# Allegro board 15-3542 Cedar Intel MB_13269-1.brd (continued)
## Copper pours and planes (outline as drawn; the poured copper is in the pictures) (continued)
RTC_AUX_S5 on TOP: 120.05,54.21 117.96,56.3 117.96,59.73 117.6,60.08 117.6,61.14 114.82,63.93 114.82,67.06 114.12,67.76 114.12,68.9 113.1,69.92 113.1,72.01 113.23,72.14 113.87,72.14 113.99,72.01 113.99,70.62 114.75,69.86 114.75,69.41 115.01,69.16 115.01,67.98 115.94,67.05 115.94,63.92 117.12,62.74 117.12,62.5 117.37,62.25 117.96,62.25 118.36,62.65 119.54,62.65 119.64,62.55 119.64,61.47 119.64,61.47 119.64,60.26 120.34,59.55 121.54,59.55 123.27,61.29 124.01,61.29 124.15,61.14 124.15,60.49 122.71,59.05 119.48,59.05 119.3,58.87 119.3,57.42 121.05,55.67 122.07,55.67 122.15,55.59 122.15,54.52 121.83,54.21 ; 5 cut-outs
SLEEVE on BOTTOM: 32.87,14.82 31.46,16.24 31.46,17.01 31.48,17.03 34.24,17.03 35.67,15.61 35.67,15.04 35.46,14.82
SLEEVE_R on TOP: 22.49,4.77 22.35,4.91 22.35,5.74 22.15,5.95 20.91,5.95 20.7,6.16 20.7,6.97 20.88,7.16 23.53,7.16 23.69,6.99 23.69,4.86 23.61,4.77
SP_PLLVDD on TOP: 169.77,101.21 169.67,101.31 169.67,101.89 169.44,102.12 168.42,102.12 168.31,102.23 168.31,107.85 168.09,108.07 168.09,110.36 168.22,110.48 169.49,110.48 169.74,110.23 169.74,103.12 170.51,102.35 170.51,101.31 170.41,101.21 ; 4 cut-outs
TP_VDD on TOP: 134.14,73.8 134.14,73.14 134.16,73.12 134.39,73.12 134.41,73.14 134.41,73.8 134.8,73.8 134.82,73.78 134.82,72.57 134.75,72.49 133.97,72.49 133.42,73.04 132.72,73.04 132.37,73.39 132.37,74.5 132.46,74.59 133.19,74.59 133.27,74.51 133.27,74.02 133.49,73.8
TPAN_VDD_F on TOP: 31.87,70.89 31.75,71.01 31.75,75.41 30.61,76.55 30.61,77.58 30.77,77.74 31.11,77.74 31.67,77.18 33.02,77.18 34.19,76.01 34.19,71.09 33.98,70.89 ; 2 cut-outs
TPS51216_PHS_SET on BOTTOM: 93.83,16.5 93.72,16.6 93.72,18.46 93.75,18.49 94.36,18.49 94.41,18.45 94.41,17.59 94.54,17.47 95.17,17.47 95.27,17.37 95.27,16.58 95.2,16.5
USB20_VCCA on TOP: 39.52,32.3 39.39,32.43 39.39,34.83 39.59,35.02 41.42,35.02 41.56,34.89 41.56,32.51 41.35,32.3
USB20_VCCA on TOP: 23.62,30.88 23.43,31.07 23.43,33.45 23.4,33.48 23.4,36.57 21.28,38.69 16.6,38.69 16.22,39.07 16.22,42.8 14.37,44.65 11.73,44.65 11.47,44.91 11.47,46.85 11.64,47.02 16.24,47.02 20.27,42.99 24.31,42.99 24.5,42.8 24.5,40.59 25.53,39.56 25.53,31.85 25.69,31.69 27.36,31.69 27.41,31.64 27.41,30.93 27.36,30.88 ; 5 cut-outs
USB20_VCCA on BOTTOM: 24.01,30.95 23.86,31.11 23.86,36.09 29.18,41.41 35.56,41.41 37.36,39.61 37.36,37.22 40.85,33.74 40.85,32.55 40.5,32.2 35.78,32.2 34.18,33.8 34.18,36.8 34.67,37.29 34.67,38.2 33.94,38.93 30.21,38.93 26.84,35.55 26.84,31.11 26.68,30.95
USB20_VCCA on BOTTOM: 12.09,44.7 11.66,45.13 11.66,46.93 11.76,47.03 15.03,47.03 15.52,46.55 15.52,44.95 15.26,44.7
USB20_VCCB on TOP: 181.61,4.17 181.31,4.47 181.31,5.45 182.88,5.45 182.88,5.85 182.58,5.85 182.58,5.85 181.31,5.85 181.31,6.46 182.9,6.46 182.9,6.85 181.31,6.85 181.31,7.45 182.91,7.45 182.91,7.85 182.5,7.85 182.5,7.85 181.31,7.85 181.31,8.33 181.46,8.48 186.16,8.48 186.96,7.68 186.96,4.51 186.62,4.17
USB20_VCCB on BOTTOM: 150.08,1.99 149.82,2.25 149.82,4.38 149.95,4.52 154.88,4.52 156.77,6.41 156.77,7.65 156.84,7.71 159.68,7.71 160.77,8.8 163.93,8.8 165.02,7.71 166.59,7.71 168.47,9.58 169.51,9.58 172.36,12.44 181.65,12.44 186.95,7.13 186.95,5.56 186.91,5.52 181.34,5.52 181.13,5.73 181.13,8.78 180.17,9.74 173.5,9.74 168.89,5.12 159.14,5.12 156,1.99 ; 5 cut-outs
USB30_VCCC on TOP: 35.29,34.11 35.17,34.24 35.17,35.98 35.3,36.12 36.76,36.12 36.9,35.98 36.9,34.44 36.57,34.11
USB30_VCCC on TOP: 14.87,27.42 14.57,27.72 14.57,28.26 14.47,28.37 14.47,30.29 14.86,30.68 19.2,30.68 19.2,30.68 23.43,30.68 23.44,30.68 27.28,30.68 27.37,30.59 27.37,29.33 27.22,29.19 25.47,29.19 25.34,29.07 25.34,27.56 25.2,27.42 ; 6 cut-outs
USB30_VCCC on L3: 27.27,30.76 24.32,30.76 24.01,30.45 24.01,28.65 24.17,28.49 28.71,28.49 33.04,32.82 36.52,32.82 36.74,33.05 36.74,35.38 36.42,35.71 35.68,35.71 35.26,35.29 31.79,35.29
VGA_CORE on TOP: 164.23,110.74 164.16,110.8 164.16,111.76 163.65,112.27 163.65,113.91 164.03,114.29 164.54,114.29 164.92,113.91 165.93,113.91 166.19,114.17 166.57,114.17 166.82,113.91 167.84,113.91 168.09,114.17 168.6,114.17 168.86,113.91 169.85,113.91 170.1,114.17 170.57,114.17 170.64,114.1 170.64,113.55 170.4,113.31 170.22,113.31 170.07,113.15 170,113.15 169.74,112.9 168.86,112.9 168.6,113.15 168.09,113.15 167.97,113.02 166.82,113.02 166.7,113.15 164.28,113.15 164.03,112.9 164.03,112.64 164.54,112.13 166.44,112.13 166.57,112.01 166.57,111.5 166.44,111.37 165.17,111.37 164.92,111.12 164.92,110.86 164.79,110.74
VGA_CORE on TOP: 164.28,117.6 164.16,117.72 164.16,118.36 164.41,118.61 168.47,118.61 169.11,119.25 169.49,119.25 170.38,118.36 171.4,118.36 171.52,118.23 171.52,117.72 171.4,117.6 ; 5 cut-outs
VGA_CORE on TOP: 164.28,115.44 164.16,115.56 164.16,116.2 164.41,116.45 171.4,116.45 171.65,116.2 171.65,115.56 171.52,115.44 ; 1 cut-out
VGA_CORE on TOP: 174.19,69.66 173.68,70.17 173.68,91.86 170.35,95.19 160.98,95.19 160.72,95.46 160.72,99.32 160.73,99.33 160.73,104.51 160.98,104.76 160.98,104.79 162.38,104.79 163.09,104.08 165.78,104.08 166.08,103.78 166.08,102.62 165.82,102.35 164.3,102.35 164.08,102.13 164.08,101.21 164.43,100.86 166.82,100.86 167.33,100.35 172.72,100.35 173.2,99.86 173.2,99.1 173.59,98.71 176.15,98.71 176.16,98.71 176.86,98.71 179.36,96.21 182.7,96.21 183.67,95.24 183.67,93.59 182.06,91.99 182.06,83.89 180.26,82.08 180.26,70.63 179.3,69.66 ; 11 cut-outs
VGA_CORE on BOTTOM: 163.65,110.1 163.01,110.74 163.01,119.12 164.16,120.26 164.54,120.26 164.79,120.01 164.79,119.88 163.39,118.48 163.39,118.36 163.78,117.98 164.03,117.98 165.93,119.88 166.32,119.88 166.44,119.75 166.44,119.5 163.39,116.45 163.39,116.2 163.65,115.94 164.03,115.94 167.84,119.75 168.22,119.75 168.35,119.63 168.35,119.37 163.52,114.55 163.52,114.17 163.65,114.04 164.03,114.04 169.74,119.75 170,119.75 170.25,119.5 170.25,119.37 163.52,112.64 163.52,112.13 163.65,112.01 164.03,112.01 171.78,119.75 172.03,119.75 172.28,119.5 172.28,119.37 164.41,111.5 164.41,111.25 164.66,110.99 164.92,110.99 171.78,117.85 172.16,117.85 172.28,117.72 172.28,117.34 166.32,111.37 166.19,111.37 165.93,111.12 165.93,110.86 166.19,110.61 166.57,110.61 171.9,115.94 172.16,115.94 172.41,115.69 172.41,115.56 168.09,111.25 168.09,110.86 168.22,110.74 168.73,110.74 171.9,113.91 172.03,113.91 172.28,113.66 172.28,113.4 170,111.12 170,110.74 170.13,110.61 170.63,110.61 171.78,111.75 172.03,111.75 172.28,111.5 172.28,111.25 171.14,110.1
VGA_CORE on BOTTOM: 174.32,68.78 173.68,69.41 173.68,91.81 173.63,91.81 170.36,95.09 164.51,95.09 164.41,95.19 164.41,95.7 164.67,95.95 173.05,95.95 173.07,95.98 173.84,95.22 174.06,95.22 174.29,94.99 183.18,94.99 183.61,94.56 183.61,69.02 183.36,68.78
VGA_CORE on L2VCC: 174.27,69.73 173.75,70.25 173.75,91.71 170.33,95.13 163.35,95.13 162.57,95.91 162.57,118.48 163.6,119.51 173.1,119.51 174,118.61 174,113.4 184.16,103.24 184.16,94.25 181.75,91.84 181.75,83.97 179.97,82.19 179.97,70.76 178.94,69.73
VGA_CORE on L3: 163.35,105.27 162.99,105.63 162.99,118.97 163.47,119.45 170.56,119.45 172.82,117.19 172.82,114.67 173.23,114.27 173.23,111.9 172.51,111.19 172.51,109.8 172.05,109.34 172.05,108.63 178.2,102.48 178.2,102.43 179.09,101.54 181.18,101.54 185.49,97.22 185.49,78.94 186.26,78.17 186.26,70.17 185.49,69.41 174.06,69.41 173.68,69.79 173.68,91.89 170.41,95.17 161.72,95.17 160.73,96.16 160.73,101.08 163.35,103.7
VGA_CORE on L4: 183.59,78.3 175.33,70.05 174.19,70.05 173.68,70.55 173.68,91.86 170.41,95.14 163.83,95.14 162.63,96.33 162.63,103.45 163.4,104.21 163.4,117.54 163.9,118.05 168.73,118.05 169.36,117.42 169.36,110.05 168.73,109.42 168.73,108.27 176.6,100.4 181.05,100.4 183.59,97.86
VRAM_PWR_PH on BOTTOM: 162.13,56.71 161.36,57.47 161.36,58.11 161.24,58.23 160.22,58.23 160.09,58.36 160.09,59.38 160.22,59.5 161.36,59.5 162.51,60.65 165.05,60.65 165.17,60.52 165.17,56.84 165.05,56.71

Small or netless copper shapes (teardrops, artwork), in the pictures only: 14 on TOP, 2 on BOTTOM

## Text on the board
Ref Des/Silkscreen Bottom: F5401:1.1A/6V | X1801:24MHZ | X3001:25MHZ | X1901:32.768KHZ | F6201:0.5A/6V | X7601:27MHZ | 13269-1 | MADE IN TAIWAN | Cedar_Intel-MB | PWB. FX3MC REV:A00
User.Comments: KING_1 | KING
Ref Des/Silkscreen Top: F5203:1.1A/24V | F5201:1.1A/24V
User.26: HEADER:EMN compare:1=show;2=show;3=show;4=show
User.33: ByImpedance:100.0@_REF_L1=("4.0/6.0(L1)" "5.0/11.0(L1)")|_REF_L6=("4.0/6.0(L6)" "5.0/11.0(L6)")|Type="DP"|_REF_L4=("4.0/9.0(L4)")|_REF_L3=("4.0/9.0(L3)")|imp="100.0" | ByImpedance:110.0@_REF_L1=("4.0/12.0(L1)")|_REF_L6=("4.0/12.0(L6)")|Type="DP"|_REF_L4=("3.5/13.0(L4)")|_REF_L3=("3.5/13.0(L3)")|imp="110.0" | ByImpedance:27.4@_REF_L1=("16.0(L1)")|_REF_L6=("16.0(L6)")|Type="SE"|_REF_L4=("16.0(L4)")|_REF_L3=("16.0(L3)")|imp="27.4" | ByImpedance:33.0@_REF_L1=("12.0(L1)")|_REF_L6=("12.0(L6)")|Type="SE"|_REF_L4=("12.0(L4)")|_REF_L3=("12.0(L3)")|imp="33.0" | ByImpedance:35.0@_REF_L1=("11.0(L1)")|_REF_L6=("11.0(L6)")|Type="SE"|_REF_L4=("10.5(L4)")|_REF_L3=("10.5(L3)")|imp="35.0" | ByImpedance:37.5@_REF_L1=("10.0(L1)")|_REF_L6=("10.0(L6)")|Type="SE"|_REF_L4=("9.5(L4)")|_REF_L3=("9.5(L3)")|imp="37.5" | ByImpedance:40.0@_REF_L1=("8.5(L1)")|_REF_L6=("8.5(L6)")|Type="SE"|_REF_L4=("8.5(L4)")|_REF_L3=("8.5(L3)")|imp="40.0" | ByImpedance:45.0@_REF_L1=("7.0(L1)")|_REF_L6=("7.0(L6)")|Type="SE"|_REF_L4=("6.5(L4)")|_REF_L3=("6.5(L3)")|imp="45.0" | ByImpedance:48.0@_REF_L1=("6.0(L1)")|_REF_L6=("6.0(L6)")|Type="SE"|_REF_L4=("5.5(L4)")|_REF_L3=("5.5(L3)")|imp="48.0" | ByImpedance:50.0@_REF_L1=("5.5(L1)")|_REF_L6=("5.5(L6)")|Type="SE"|_REF_L4=("5.0(L4)")|_REF_L3=("5.0(L3)")|imp="50.0" | ByImpedance:52.0@_REF_L1=("5.0(L1)")|_REF_L6=("5.0(L6)")|Type="SE"|_REF_L4=("4.5(L4)")|_REF_L3=("4.5(L3)")|imp="52.0" | ByImpedance:55.0@_REF_L1=("4.5(L1)")|_REF_L6=("4.5(L6)")|Type="SE"|_REF_L4=("4.0(L4)")|_REF_L3=("4.0(L3)")|imp="55.0" | ByImpedance:60.0@_REF_L1=("3.5(L1)")|_REF_L6=("3.5(L6)")|Type="SE"|_REF_L4=("nil(L4)")|_REF_L3=("nil(L3)")|imp="60.0" | ByImpedance:65.0@_REF_L1=("10.0/5.0(L1)")|_REF_L6=("10.0/5.0(L6)")|Type="DP"|_REF_L4=("9.0/5.0(L4)")|_REF_L3=("9.0/5.0(L3)")|imp="65.0" | ByImpedance:70.0@_REF_L1=("8.5/5.0(L1)")|_REF_L6=("8.5/5.0(L6)")|Type="DP"|_REF_L4=("8.0/6.0(L4)")|_REF_L3=("8.0/6.0(L3)")|imp="70.0" | ByImpedance:72.0@_REF_L1=("8.0/5.0(L1)")|_REF_L6=("8.0/5.0(L6)")|Type="DP"|_REF_L4=("7.0/5.0(L4)")|_REF_L3=("7.0/5.0(L3)")|imp="72.0" | ByImpedance:75.0@_REF_L1=("7.0/4.5(L1)")|_REF_L6=("7.0/4.5(L6)")|Type="DP"|_REF_L4=("7.0/6.0(L4)")|_REF_L3=("7.0/6.0(L3)")|imp="75.0" | ByImpedance:80.0@_REF_L1=("5.5/4.0(L1)" "6.0/4.5(L1)")|_REF_L6=("5.5/4.0(L6)" "6.0/4.5(L6)")|Type="DP"|_REF_L4=("6.0/6.0(L4)" "5.0/4.0(L4)")|_REF_L3=("6.0/6.0(L3)" "5.0/4.0(L3)")|imp="80.0" | ByImpedance:85.0@_REF_L1=("5.0/4.5(L1)" "6.0/6.0(L1)")|_REF_L6=("5.0/4.5(L6)" "6.0/6.0(L6)")|Type="DP"|_REF_L4=("5.0/5.5(L4)" "4.5/4.5(L4)")|_REF_L3=("5.0/5.5(L3)" "4.5/4.5(L3)")|imp="85.0" | ByImpedance:90.0@_REF_L1=("4.0/4.0(L1)" "5.5/7.0(L1)" "5.0/6.0(L1)")|_REF_L6=("4.0/4.0(L6)" "5.5/7.0(L6)" "5.0/6.0(L6)")|Type="DP"|_REF_L4=("5.0/8.0(L4)" "4.0/5.0(L4)" "5.5/10.0(L4)")|_REF_L3=("5.0/8.0(L3)" "4.0/5.0(L3)" "5.5/10.0(L3)")|imp="90.0" | ByImpedance:93.0@_REF_L1=("4.0/4.5(L1)" "5.0/6.5(L1)")|_REF_L6=("4.0/4.5(L6)" "5.0/6.5(L6)")|Type="DP"|_REF_L4=("5.0/9.0(L4)" "4.0/5.5(L4)")|_REF_L3=("5.0/9.0(L3)" "4.0/5.5(L3)")|imp="93.0" | ByImpedance:95.0@_REF_L1=("4.5/6.0(L1)")|_REF_L6=("4.5/6.0(L6)")|Type="DP"|_REF_L4=("4.0/6.5(L4)")|_REF_L3=("4.0/6.5(L3)")|imp="95.0" | LayerIndex:nil | Source:6-1.3-4c.xls | artWorks:("_REF_L3" "_REF_L4" "_REF_L6" "_REF_L1") | gtImpOutlineUsed:BOARD GEOMETRY/PANEL_OUTLINE
User.34: Board Accuracy Check,Feb 12 16:42:26 2014,Passed | Component Overlap Check,Nov 14 09:57:02 2013,121 errors | Dummy-Static-No Shape On Layer Check,Feb 12 16:42:27 2014,Passed | Proper Pad Entry Check,Feb 11 21:57:16 2014,1233 errors | Split Plane Check,Feb 11 22:49:32 2014,Passed | TP Violations Check,Nov 13 16:30:35 2013,1114 errors | Via On Moat Check,Nov 14 09:57:03 2013,47 errors
User.45: AUD_AGND | GND | VCC_CORE | 1D05V_S0 | DCBATOUT | VGA_CORE | Note:Refer to DRILL layer for ELLIPSE drill direction | FIGURE | SIZE | 10.0 | 16.0 | 21.0 | 28.0 | 30.0 | 32.0 | 36.0 | 37.0 | 40.0 | 115.0 | 117.0 | 166.0 | 42.0 | 44.0 | 46.0 | 48.0 | 50.0 | 52.0 | 63.0 | 69.0 | 86.0 | 138.0 | 140.0 | 158.0 | 60.0x24.0 | 71.0x36.0 | 83.0x28.0 | 91.0x36.0 | 95.0x28.0 | 95.0x36.0 | 95.0x40.0 | 98.0x28.0 | 109.0x28.0 | 178.0x138.0 | DRILL CHART: TOP to BOTTOM | ALL UNITS ARE IN MILS | PLATED | NON-PLATED | QTY | 3129 | 978 | 19 | 9 | 28 | 7 | 8 | 4 | 6 | 2 | 3 | 1 | This gerber is just for your reference to find the DP impedance traces in layer L1. | This gerber is just for your reference to find the DP impedance traces in layer L3. | This gerber is just for your reference to find the DP impedance traces in layer L4. | This gerber is just for your reference to find the DP impedance traces in layer L6. | This gerber is just for your reference to find the SE impedance traces in layer L1. | This gerber is just for your reference to find the SE impedance traces in layer L3. | This gerber is just for your reference to find the SE impedance traces in layer L4. | This gerber is just for your reference to find the SE impedance traces in layer L6. | DP IMPEDANCE TABLE: L1 | DP IMPEDANCE TABLE: L3 | DP IMPEDANCE TABLE: L4 | DP IMPEDANCE TABLE: L6 | SE IMPEDANCE TABLE: L1 | SE IMPEDANCE TABLE: L3 | SE IMPEDANCE TABLE: L4 | SE IMPEDANCE TABLE: L6 | * - Denotes that WIDTH | is NOT used in this layer | inside board outline. | Model | Cedar_Intel-MB | PCB_NO | 13269 | VER. | Layer | DRILL | L1 | L2VCC | L3 | TMASK | TPLACE | TSILK | TSMD | Designer | WPH-CRIS | Date | 2014/02/12 | IMP(Ohm) | 27.4 | 65.0 | 33.0 | 70.0 | 35.0 | 72.0 | 37.5 | 75.0 | 80.0 | 45.0 | 85.0 | 90.0 | 55.0 | 60.0 | 93.0 | 95.0 | 100.0 | 110.0 | WIDTH(mils) | *16.0 | 12.0 | *10.5 | *11.0 | *9.5 | *8.5 | 8.5 | 6.5 | 7.0 | *5.5 | *6.0 | 6.0 | 5.0 | 5.5 | *4.5 | 4.0 | *3.5 | *nil | 3.5 | *10.0/5.0 | *9.0/5.0 | 10.0/5.0 | *8.0/6.0 | *8.5/5.0 | *7.0/5.0 | *8.0/5.0 | *7.0/4.5 | *7.0/6.0 | *6.0/6.0 | 5.5/4.0 | *6.0/4.5 | 5.0/4.0 | *5.0/5.5 | 5.0/4.5 | 4.5/4.5 | *4.0/4.0 | *5.0/8.0 | 4.0/4.0 | *5.5/7.0 | 4.0/5.0 | *5.0/6.0 | *5.5/10.0 | *4.0/4.5 | *5.0/9.0 | *4.0/5.5 | *5.0/6.5 | *4.0/6.5 | *4.5/6.0 | *4.0/9.0 | 4.0/6.0 | *3.5/13.0 | *5.0/11.0 | *4.0/12.0 | TYPE | SE | DP | BMASK | BPLACE | BSILK | BSMD | L4 | L5GND | L6
